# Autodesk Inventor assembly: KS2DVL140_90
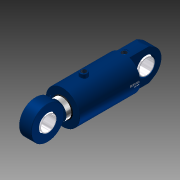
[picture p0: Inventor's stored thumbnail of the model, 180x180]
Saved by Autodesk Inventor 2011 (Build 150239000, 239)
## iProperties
Created: 2010-11
Document SubType Name: Assembly
Designer: TB
Mass: 566.294 g
Surface Area: 1153.75 cm^2
Volume: 566.294 cm^3
Density: 1 g/cm^3
Description: KS2DVL 140/90 - 100 mm
Slaglengde: 100,000 mm
Author: TB
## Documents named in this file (6)
- C:\Vault\Sylinderteknikk\Projects_ST\3D.nettkatalog\KS2-Series\KS2DVL\KS2DVL140_90\KS2DVL140_90.iam
- C:\Vault\Sylinderteknikk\Projects_ST\3D.nettkatalog\KS2-Series\KS2DVL\KS2DVL140_90\KS2DVL140_90_stang.ipt
- C:\Vault\Sylinderteknikk\Projects_ST\3D.nettkatalog\KS2-Series\KS2DVL\KS2DVL140_90\KS2DVL140_90_Parameters.ipt
- C:\Vault\Sylinderteknikk\Projects_ST\3D.nettkatalog\KS2-Series\KS2DVL\KS2DVL140_90\KS2DVL140_90_body..ipt
- C:\Vault\Sylinderteknikk\Projects_ST\Øyer\Klinkby.KS.Øyer\KS.70.eye.komplett\KS.70.eye.komplett.ipt
- C:\Vault\Sylinderteknikk\Projects_ST\Øyer\Klinkby.KS.Øyer\KS.70.eye.komplett\Kule70HO.ipt
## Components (5 placed, 5 different names)
1. KS2DVL140_90_Parameters:3
2. KS2DVL140_90_stang:1 — Mate:1, FriMate:2, Mate:3, Insert:1
3. KS2DVL140_90_body.:1 — Mate:1, FriMate:2, Mate:3, Angle:1, Insert:2
4. KS.70.eye.komplett:1 — Insert:1, Angle:1
5. Kule70HO:1 — Insert:2
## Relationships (6: Mate 3, Insert 2, Angle 1)
- Mate:1: KS2DVL140_90_stang:1 ↔ KS2DVL140_90_body.:1
- FriMate:2 [Mate]: KS2DVL140_90_stang:1 ↔ KS2DVL140_90_body.:1
- Mate:3: KS2DVL140_90_stang:1 ↔ KS2DVL140_90_body.:1
- Insert:1: KS2DVL140_90_stang:1 ↔ KS.70.eye.komplett:1
- Angle:1: KS2DVL140_90_body.:1 ↔ KS.70.eye.komplett:1
- Insert:2: KS2DVL140_90_body.:1 ↔ Kule70HO:1
## Named parameters: Forlengelse_rør = 0, Vinkel_Minusport = 0
